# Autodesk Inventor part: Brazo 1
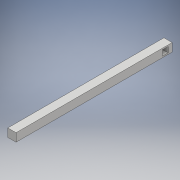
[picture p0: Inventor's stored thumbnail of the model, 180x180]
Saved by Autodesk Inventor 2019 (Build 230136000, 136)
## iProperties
Created: 2019-02
Part Number: Brazo 1
Material: Genérico
Document SubType Name: Modeling
Designer: Juan Manuel Montalvo Navarrete
Density: 1 g/cm^3
Appearance: Valor por defecto
Author: Juan Manuel Montalvo Navarrete
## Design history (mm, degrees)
sketch "Boceto1"
  geometry: L1 (15, 15)-(-15, 15); L2 (-15, 15)-(-15, -15); L3 (-15, -15)-(15, -15); L4 (15, -15)-(15, 15); L5 (15, 15)-(-15, -15); L6 (-15, 15)-(15, -15); 1 further point
  constraints: 12 end point, 2 midpoint, 2 parallel, 1 horizontal, 1 perpendicular
  dimensions: "d0" = 30 distance of L3.end L2.end; "d1" = 30 distance of L2.end L1.end
extrude "Extrusión1" new body sketch "Boceto1" distance "d2" = 568; taper "d3" = 0 deg
sketch "Boceto3"
  geometry: L1 (5, -15)-(25, -15); L2 (25, -15)-(25, -35); L3 (25, -35)-(5, -35); L4 (5, -35)-(5, -15); L5 (5, -15)-(25, -35); L6 (25, -15)-(5, -35); L7 (0, 0)-(30, 0) reference; L8 (0, -568)-(0, 0) reference; 3 further points
  constraints: 12 end point, 2 midpoint, 2 parallel, 1 horizontal, 1 perpendicular
  dimensions: "d8" = 20 distance of L2.end L3.end; "d9" = 20 distance of L1.end L2.end; "d10" = 15 distance between parallel lines of L7 L1; "d11" = 5 distance between parallel lines of L8 L4
extrude "Extrusión3" cut sketch "Boceto3" extent not by distance; stored distance "d12" = 0; taper "d13" = 0 deg
node "Sólido1"
